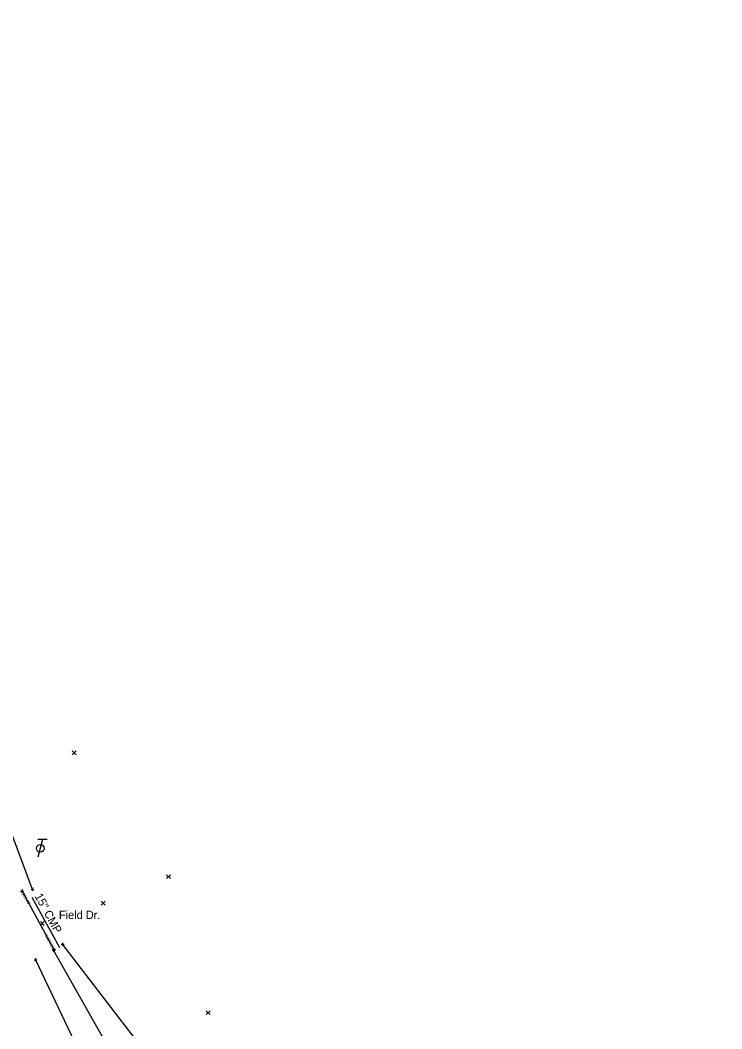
# Model space of a CAD drawing. Extents: x 2298098 to 2302860, y 557788 to 564251.
# Drawn here: x 2299738 to 2299977.1, y 561245.7 to 561589.4 of the extents above; entities that cross this region are included whole.
import ezdxf

# ---------------------------------------------------------------- set-up
doc = ezdxf.new("R2010")
doc.units = 0
for name, color, linetype in [('DR_X_Ditch', 7, 'Continuous'), ('DR_X_Elev_Flow', 7, 'Continuous'), ('DR_X_Storm_Sewer', 7, 'Continuous'), ('DR_X_Text', 7, 'Continuous'), ('PV_X_Text', 7, 'Continuous'), ('SC_Scratch1', 7, 'Continuous'), ('SV_X_Break_Lines', 7, 'Continuous'), ('SV_X_Random_Point', 7, 'Continuous'), ('SV_X_Shot_Marker', 7, 'Continuous'), ('UT_X_Telecom_Cells', 7, 'Continuous')]:
    doc.layers.add(name, color=color, linetype=linetype)

msp = doc.modelspace()

# ---------------------------------------------------------------- linework, layer by layer
at = {"layer": 'DR_X_Ditch'}
msp.add_lwpolyline([(2299947.33, 560900.77), (2299933.75, 560925.88), (2299911.49, 560968.04), (2299888.52, 561013.62), (2299864.88, 561059.66), (2299843.49, 561104.65), (2299821.62, 561147.64), (2299797.59, 561193.32), (2299770.88, 561234.4), (2299749.36, 561272.5)], dxfattribs=at)
at = {"layer": 'DR_X_Elev_Flow'}
for p, q in [((2299738.1, 561292.66), (2299739.1, 561292.66)), ((2299738.6, 561293.16), (2299738.6, 561292.16)), ((2299738.6, 561292.66), (2299738.6, 561292.66)), ((2299748.97, 561272.75), (2299749.97, 561272.75)), ((2299749.47, 561273.25), (2299749.47, 561272.25)), ((2299749.47, 561272.75), (2299749.47, 561272.75))]:
    msp.add_line(p, q, dxfattribs=at)
at = {"layer": 'DR_X_Storm_Sewer'}
msp.add_line((2299738.6, 561292.66), (2299749.47, 561272.75), dxfattribs=at)
at = {"layer": 'DR_X_Text'}
msp.add_line((2299751.45, 561273.35), (2299742.09, 561290.49), dxfattribs=at)
at = {"layer": 'SV_X_Break_Lines'}
for points in [[(2299742.16, 561293.21), (2299730.03, 561325.53), (2299707.75, 561369.5), (2299687.14, 561416.12), (2299664.66, 561463.85), (2299643.3, 561508.16), (2299618.73, 561545.83), (2299590.25, 561589.38)], [(2299977.08, 560851.92), (2299962.79, 560885.63), (2299943.44, 560930.04), (2299922.12, 560972.96), (2299899.62, 561024.1), (2299876.86, 561061.88), (2299856.06, 561110.09), (2299831.14, 561154.42), (2299808.16, 561196.66), (2299781, 561237.26), (2299752.42, 561274.51)], [(2299743.18, 561269.26), (2299761.95, 561229.81), (2299785.6, 561185.67), (2299809.04, 561141.23), (2299831.82, 561097.39), (2299855.54, 561053.53), (2299878.79, 561009.46), (2299902.19, 560965.55), (2299925.95, 560921.19), (2299951.18, 560878.72)]]:
    msp.add_lwpolyline(points, dxfattribs=at)
at = {"layer": 'SV_X_Random_Point'}
for p, q in [((2299755.7, 561339.05), (2299757.03, 561340.38)), ((2299755.7, 561340.38), (2299757.03, 561339.05)), ((2299787.86, 561296.89), (2299789.19, 561298.23)), ((2299787.86, 561298.23), (2299789.19, 561296.89)), ((2299765.59, 561287.84), (2299766.92, 561289.18)), ((2299765.59, 561289.18), (2299766.92, 561287.84)), ((2299744.84, 561280.96), (2299746.17, 561282.29)), ((2299744.84, 561282.29), (2299746.17, 561280.96)), ((2299801.33, 561250.55), (2299802.66, 561251.89)), ((2299801.33, 561251.89), (2299802.66, 561250.55))]:
    msp.add_line(p, q, dxfattribs=at)
at = {"layer": 'SV_X_Shot_Marker'}
for p, q in [((2299742.16, 561293.71), (2299742.16, 561292.71)), ((2299741.66, 561293.21), (2299742.66, 561293.21)), ((2299742.16, 561293.21), (2299742.16, 561293.21)), ((2299749.36, 561273), (2299749.36, 561272)), ((2299751.92, 561274.51), (2299752.92, 561274.51)), ((2299752.42, 561275.01), (2299752.42, 561274.01)), ((2299752.42, 561274.51), (2299752.42, 561274.51)), ((2299742.68, 561269.26), (2299743.68, 561269.26)), ((2299743.18, 561269.76), (2299743.18, 561268.76)), ((2299743.18, 561269.26), (2299743.18, 561269.26)), ((2299748.86, 561272.5), (2299749.86, 561272.5)), ((2299749.36, 561272.5), (2299749.36, 561272.5))]:
    msp.add_line(p, q, dxfattribs=at)
at = {"layer": 'UT_X_Telecom_Cells'}
for p, q in [((2299745.61, 561310.2), (2299744, 561304.2)), ((2299747.21, 561310.2), (2299744.01, 561310.2))]:
    msp.add_line(p, q, dxfattribs=at)
msp.add_circle((2299744.81, 561307.2), 1.3, dxfattribs=at)

# ---------------------------------------------------------------- texts
at = {"layer": 'DR_X_Text'}
msp.add_text('15" CMP', height=2.8, rotation=298.629, dxfattribs=at).set_placement((2299742.79, 561290.93))
at = {"layer": 'PV_X_Text'}
msp.add_text('Field Dr.', height=2.8, dxfattribs=at).set_placement((2299751.16, 561283.13))
at = {"layer": 'SC_Scratch1'}
for s, p in [("1126.65'", (2299738.16, 561292.42)), ("1,124.96'", (2299746.25, 561277.6))]:
    msp.add_text(s, height=1, rotation=298.629, dxfattribs=at).set_placement(p)

doc.saveas('drawing.dxf')
